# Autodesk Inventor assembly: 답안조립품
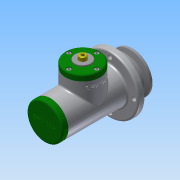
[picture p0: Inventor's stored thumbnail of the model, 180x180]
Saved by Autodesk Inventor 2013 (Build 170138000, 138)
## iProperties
Created: 2016-08
Part Number: 답안조립품
Document SubType Name: Assembly
Designer: Administrator
Author: Administrator
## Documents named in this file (25)
- C:\Users\Administrator\Desktop\460808V1001\답안조립품.iam
- C:\Users\Administrator\Desktop\460808V1001\본체.ipt
- C:\Users\Administrator\Desktop\460808V1001\사이드 커버.ipt
- 사이드 커버.ipt
- C:\Users\Administrator\Desktop\460808V1001\탑 부시.ipt
- C:\Users\Administrator\Desktop\460808V1001\탑 커버.ipt
- 탑 커버.ipt
- C:\Users\Administrator\Desktop\460808V1001\볼트 M4 x 12.ipt
- C:\Users\Administrator\Desktop\460808V1001\오일 실 15 25 7.ipt
- C:\Users\Administrator\Desktop\460808V1001\편심축.ipt
- C:\Users\Administrator\Desktop\460808V1001\링크.ipt
- C:\Users\Administrator\Desktop\460808V1001\클래스터 핀 6 x 24.ipt
- C:\Users\Administrator\Desktop\460808V1001\분할핀 1.6 x 12.ipt
- C:\Users\Administrator\Desktop\460808V1001\부시1.ipt
- C:\Users\Administrator\Desktop\460808V1001\슬라이더.ipt
- C:\Users\Administrator\Desktop\460808V1001\베어링 15 x 35 x 11.ipt
- C:\Users\Administrator\Desktop\460808V1001\멈춤링 15 x 1.ipt
- C:\Users\Administrator\Desktop\460808V1001\멈춤링 35x1.6.ipt
- C:\Users\Administrator\Desktop\460808V1001\부시2.ipt
- C:\Users\Administrator\Desktop\460808V1001\와셔 10x21.ipt
- C:\Users\Administrator\Desktop\460808V1001\너트 M10.ipt
- C:\Users\Administrator\Desktop\460808V1001\V-벨트풀리.ipt
- C:\Users\Administrator\Desktop\460808V1001\키 4 x 4 x 18.ipt
- C:\Users\Administrator\Desktop\460808V1001\볼트 M4 x 10.ipt
- C:\Users\Administrator\Desktop\460808V1001\와셔 4x16.ipt
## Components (6 placed, 3 different names)
1. V-벨트풀리:1
2. ISO 4017 M4 x 10:1
3. ISO 4762 M4 x 12:1
4. ISO 4762 M4 x 12:2
5. ISO 4762 M4 x 12:3
6. ISO 4762 M4 x 12:4
